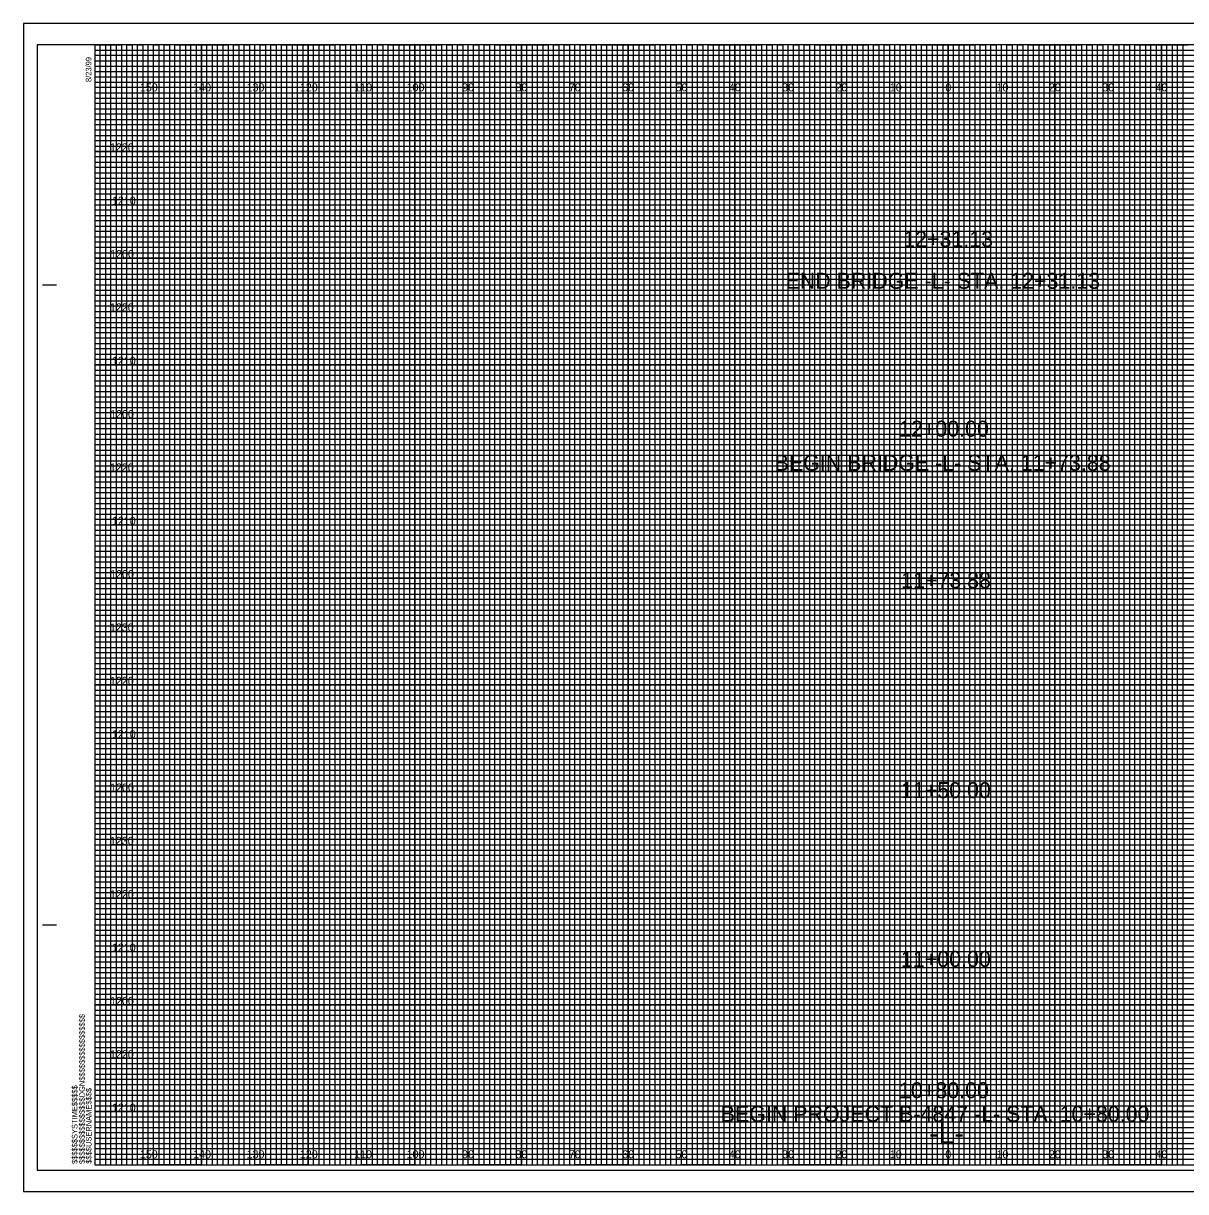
# Model space of a CAD drawing. Extents: x -13 to 375, y -5 to 214.
# Drawn here: x -13.4 to 204.5, y -5 to 214 of the extents above; entities that cross this region are included whole.
import ezdxf

# ---------------------------------------------------------------- set-up
doc = ezdxf.new("R2010")
doc.units = 0
for name, color, linetype in [('Default', 7, 'Continuous'), ('Prop XS Alignment Label', 7, 'Continuous'), ('Prop XS Elevation Labels', 7, 'Continuous'), ('Prop XS Offset Labels', 7, 'Continuous'), ('Prop XS Station Labels', 7, 'Continuous'), ('Sheet Cross Section CELL', 7, 'Continuous'), ('Sheet Cross Section Grid Major CELL', 7, 'Continuous'), ('Sheet Cross Section Grid Middle CELL', 7, 'Continuous'), ('Sheet Cross Section Grid Minor 1 CELL', 7, 'Continuous'), ('Sheet Cross Section Grid Minor 2 CELL', 7, 'Continuous'), ('Sheet Cutting Line CELL', 7, 'Continuous'), ('Sheet DOT Grid CELL', 7, 'Continuous'), ('Sheet Plot Border Inside CELL', 7, 'Continuous'), ('Sheet Plot Border Outside CELL', 7, 'Continuous')]:
    doc.layers.add(name, color=color, linetype=linetype)

msp = doc.modelspace()

# ---------------------------------------------------------------- linework, layer by layer
at = {"layer": 'Sheet Cross Section CELL'}
for p, q in [((-9.8, 165), (-7.3, 165)), ((-9.7, 165), (-7.2, 165)), ((-9.8, 45), (-7.3, 45)), ((-9.7, 45), (-7.2, 45)), ((0, 0), (0, 0)), ((0, 0), (0, 0)), ((0, 0), (0, 0)), ((0, 0), (0, 0)), ((0, 0), (0, 0)), ((0, 0), (0, 0)), ((0, 0), (0, 0))]:
    msp.add_line(p, q, dxfattribs=at)
msp.add_lwpolyline([(320, 210), (0, 210), (0, 0), (320, 0)], close=True, dxfattribs=at)
at = {"layer": 'Sheet Cross Section Grid Major CELL'}
for p, q in [((10, 210), (0, 210)), ((10, 0), (10, 210)), ((30, 210), (20, 210)), ((20, 210), (20, 0)), ((30, 0), (30, 210)), ((50, 210), (40, 210)), ((40, 210), (40, 0)), ((50, 0), (50, 210)), ((70, 210), (60, 210)), ((60, 210), (60, 0)), ((70, 0), (70, 210)), ((90, 210), (80, 210)), ((80, 210), (80, 0)), ((90, 0), (90, 210)), ((110, 210), (100, 210)), ((100, 210), (100, 0)), ((110, 0), (110, 210)), ((130, 210), (120, 210)), ((120, 210), (120, 0)), ((130, 0), (130, 210)), ((150, 210), (140, 210)), ((140, 210), (140, 0)), ((150, 0), (150, 210)), ((170, 210), (160, 210)), ((160, 210), (160, 0)), ((170, 0), (170, 210)), ((190, 210), (180, 210)), ((180, 210), (180, 0)), ((190, 0), (190, 210)), ((210, 210), (200, 210)), ((200, 210), (200, 0)), ((20, 0), (10, 0)), ((40, 0), (30, 0)), ((60, 0), (50, 0)), ((80, 0), (70, 0)), ((100, 0), (90, 0)), ((120, 0), (110, 0)), ((140, 0), (130, 0)), ((160, 0), (150, 0)), ((180, 0), (170, 0)), ((200, 0), (190, 0))]:
    msp.add_line(p, q, dxfattribs=at)
for points in [[(0, 200), (320, 200), (320, 190), (0, 190)], [(0, 180), (320, 180), (320, 170), (0, 170)], [(0, 160), (320, 160), (320, 150), (0, 150)], [(0, 140), (320, 140), (320, 130), (0, 130)], [(0, 120), (320, 120), (320, 110), (0, 110)], [(0, 100), (320, 100), (320, 90), (0, 90)], [(0, 80), (320, 80), (320, 70), (0, 70)], [(0, 60), (320, 60), (320, 50), (0, 50)], [(0, 40), (320, 40), (320, 30), (0, 30)], [(0, 20), (320, 20), (320, 10), (0, 10)]]:
    msp.add_lwpolyline(points, dxfattribs=at)
at = {"layer": 'Sheet Cross Section Grid Middle CELL'}
for points in [[(0, 210), (5, 210), (5, 0), (15, 0), (15, 210), (25, 210), (25, 0), (35, 0), (35, 210), (45, 210), (45, 0), (55, 0), (55, 210), (65, 210), (65, 0), (75, 0), (75, 210), (85, 210), (85, 0), (95, 0), (95, 210), (105, 210), (105, 0), (115, 0), (115, 210), (125, 210), (125, 0), (135, 0), (135, 210), (145, 210), (145, 0), (155, 0), (155, 210), (165, 210), (165, 0), (175, 0), (175, 210), (185, 210), (185, 0), (195, 0), (195, 210), (205, 210)], [(0, 205), (275, 205)], [(0, 185), (320, 185), (320, 195), (0, 195)], [(0, 165), (320, 165), (320, 175), (0, 175)], [(0, 145), (320, 145), (320, 155), (0, 155)], [(0, 125), (320, 125), (320, 135), (0, 135)], [(0, 105), (320, 105), (320, 115), (0, 115)], [(0, 85), (320, 85), (320, 95), (0, 95)], [(0, 65), (320, 65), (320, 75), (0, 75)], [(0, 45), (320, 45), (320, 55), (0, 55)], [(0, 25), (320, 25), (320, 35), (0, 35)], [(0, 5), (320, 5), (320, 15), (0, 15)]]:
    msp.add_lwpolyline(points, dxfattribs=at)
at = {"layer": 'Sheet Cross Section Grid Minor 1 CELL'}
for p, q in [((0, 209), (260, 209)), ((260, 207.98), (0, 207.98)), ((0, 207.98), (0, 207)), ((0, 207), (260, 207)), ((260, 205.89), (0, 205.89)), ((0, 205.89), (0, 204)), ((0, 204), (320, 204))]:
    msp.add_line(p, q, dxfattribs=at)
for points in [[(0, 203), (270, 203), (320, 203), (320, 202), (0, 202)], [(0, 201), (320, 201), (320, 199), (0, 199)], [(0, 198), (320, 198), (320, 197), (0, 196.98)], [(0, 196), (320, 196), (320, 194), (0, 194)], [(0, 193), (320, 193), (320, 192), (0, 192)], [(0, 191), (320, 191), (320, 189), (0, 189)], [(0, 188), (320, 188), (320, 187), (0, 187)], [(0, 186), (320, 186), (320, 184), (0, 184)], [(0, 183), (320, 183), (320, 182), (0, 182)], [(0, 181), (320, 181), (320, 179), (0, 179)], [(0, 178), (320, 178), (320, 177), (0, 177)], [(0, 176), (320, 176), (320, 173.95), (320, 173), (320, 172), (0, 172)], [(0, 174), (320, 174), (320, 173), (0, 173)], [(0, 171), (320, 171), (320, 169), (0, 169.03)], [(0, 169.03), (320, 169), (320, 168), (0, 168)], [(0, 167), (320, 167), (320, 166), (0, 166)], [(0, 164), (320, 164), (320, 163), (0, 163)], [(0, 162), (320, 162), (320, 161), (0, 161)], [(-0.07, 158.89), (320, 158.89), (320, 157.88), (-0.07, 157.88)], [(0, 157), (320, 157), (320, 156), (0, 156)], [(0, 154), (320, 154), (320, 153), (0, 153)], [(0, 152), (320, 152), (320, 151), (0, 151)], [(0, 149), (320, 149), (320, 148), (0, 148)], [(0, 147), (320, 147), (320, 146), (0, 146)], [(0, 144), (320, 144), (320, 143), (0, 143)], [(0, 142), (320, 142), (320, 141), (0, 141)], [(0, 139), (320, 139), (319.99, 137.98), (0, 138)], [(0, 137), (320, 137), (320, 136), (0, 136)], [(0, 134), (320, 134), (320, 133), (0, 133)], [(0, 132), (320, 132), (320, 131), (0, 131)], [(0, 129), (320, 129), (320, 128), (0, 128)], [(0, 127), (320, 127), (320, 126), (0, 126)], [(0, 124), (320, 124), (320, 123), (0, 123)], [(0, 122), (320, 122), (320, 121), (0, 121)], [(0, 119), (320, 119), (320, 118), (0, 118)], [(0, 116.99), (320.07, 116.91), (320, 116), (0, 116)], [(0, 114), (320, 114), (320, 113), (0, 113)], [(0, 112), (320, 112), (320, 111), (0, 111)], [(0, 109), (320, 109), (320, 108), (0, 108)], [(0, 107), (320, 107), (320, 106), (0, 106)], [(0, 104), (320, 104), (320, 103), (0, 103)], [(0, 102), (320, 102), (320, 101), (0, 101)], [(0, 99), (320, 99), (320, 98), (0, 98)], [(0, 97), (320, 97), (320, 96), (0, 96)], [(0, 94), (320, 94), (320, 93), (0, 93)], [(0, 92), (320, 92), (320, 91), (0, 91)], [(0, 89), (320, 89), (320, 88), (0, 88)], [(0, 87), (320, 87), (320, 86), (0, 86)], [(0, 84), (320, 84), (320, 83), (0, 83)], [(0, 82), (320, 82), (320, 81), (0, 81)], [(0, 79), (320, 79), (319.99, 77.98), (0, 78)], [(0, 77), (320, 77), (320, 76), (0, 76)], [(0, 74), (320, 74), (320, 73), (0, 73)], [(0, 72), (320, 72), (320, 71), (0, 71)], [(0, 69), (320, 69), (320, 68), (0, 68)], [(0, 67), (320, 67), (320, 66), (0, 66)], [(0, 64), (320, 64), (320, 63), (0, 63)], [(0, 62), (320, 62), (320, 61), (0, 61)], [(0, 59), (320, 59), (320, 58), (0, 58)], [(0, 56.99), (320.07, 56.91), (320, 56), (0, 56)], [(0, 54), (320, 54), (320, 53), (0, 53)], [(0, 52), (320, 52), (320, 51), (0, 51)], [(0, 49), (320, 49), (320, 48), (0, 48)], [(0, 47), (320, 47), (320, 46), (0, 46)], [(0, 44), (320, 44), (320, 43), (0, 43)], [(0, 42), (320, 42), (320, 41), (0, 41)], [(0, 39), (320, 39), (320, 38), (0, 38)], [(0, 37), (320, 37), (320, 36), (0, 36)], [(0, 34), (320, 34), (320, 33), (0, 33)], [(0, 32), (320, 32), (320, 31), (0, 31)], [(0, 29), (320, 29), (320, 28), (0, 28)], [(0, 27), (320, 27), (320, 26), (0, 26)], [(0, 24), (320, 24), (320, 23), (0, 23)], [(0, 22), (320, 22), (320, 21), (0, 21)], [(0, 19), (320, 19), (320, 18), (0, 18)], [(0, 17), (320, 17), (320, 16), (0, 16)], [(0, 14), (320, 14), (320, 13), (0, 13)], [(0, 12), (320, 12), (320, 11), (0, 11)], [(0, 9), (320, 9), (320, 8), (0, 8)], [(0, 7), (320, 7), (320, 6), (0, 6)], [(0, 4), (320, 4), (320, 3), (0, 3)], [(0, 2), (320, 2), (320, 1), (0, 1)]]:
    msp.add_lwpolyline(points, dxfattribs=at)
at = {"layer": 'Sheet Cross Section Grid Minor 2 CELL'}
for points in [[(0, 0), (1, 0), (1, 210), (2, 210), (2, 0)], [(2, 0), (3, 0), (3, 210), (4, 210), (4, 0)], [(5, 0), (6, 0), (6, 210), (7, 210), (7, 0)], [(7, 0), (8, 0), (8, 210), (9, 210), (9, 0)], [(10, 0), (11, 0), (11, 210), (12, 210), (12, 0)], [(12, 0), (13, 0), (13, 210), (14, 210), (14, 0)], [(15, 0), (16, 0), (16, 210), (17, 210), (17, 0)], [(17, 0), (18, 0), (18, 210), (19, 210), (19, 0)], [(20, 0), (21, 0), (21, 210), (22, 210), (22, 0)], [(22, 0), (23, 0), (23, 210), (24, 210), (24, 0)], [(25, 0), (26, 0), (26, 210), (27, 210), (27, 0)], [(27, 0), (28, 0), (28, 210), (29, 210), (29, 0)], [(30, 0), (31, 0), (31, 210), (32, 210), (32, 0)], [(32, 0), (33, 0), (33, 210), (34, 210), (34, 0)], [(35, 0), (36, 0), (36, 210), (37, 210), (37, 0)], [(37, 0), (38, 0), (38, 210), (39, 210), (39, 0)], [(40, 0), (41, 0), (41, 210), (42, 210), (42, 0)], [(42, 0), (43, 0), (43, 210), (44, 210), (44, 0)], [(45, 0), (46, 0), (46, 210), (47, 210), (47, 0)], [(47, 0), (48, 0), (48, 210), (49, 210), (49, 0)], [(50, 0), (51, 0), (51, 210), (52, 210), (52, 0)], [(52, 0), (53, 0), (53, 210), (54, 210), (54, 0)], [(55, 0), (56, 0), (56, 210), (57, 210), (57, 0)], [(57, 0), (58, 0), (58, 210), (59, 210), (59, 0)], [(60, 0), (61, 0), (61, 210), (62, 210), (62, 0)], [(62, 0), (63, 0), (63, 210), (64, 210), (64, 0)], [(65, 0), (66, 0), (66, 210), (67, 210), (67, 0)], [(67, 0), (68, 0), (68, 210), (69, 210), (69, 0)], [(70, 0), (71, 0), (71, 210), (72, 210), (72, 0)], [(72, 0), (73, 0), (73, 210), (74, 210), (74, 0)], [(75, 0), (76, 0), (76, 210), (77, 210), (77, 0)], [(77, 0), (78, 0), (78, 210), (79, 210), (79, 0)], [(80, 0), (81, 0), (81, 210), (82, 210), (82, 0)], [(82, 0), (83, 0), (83, 210), (84, 210), (84, 0)], [(85, 0), (86, 0), (86, 210), (87, 210), (87, 0)], [(87, 0), (88, 0), (88, 210), (89, 210), (89, 0)], [(90, 0), (91, 0), (91, 210), (92, 210), (92, 0)], [(92, 0), (93, 0), (93, 210), (94, 210), (94, 0)], [(95, 0), (96, 0), (96, 210), (97, 210), (97, 0)], [(97, 0), (98, 0), (98, 210), (99, 210), (99, 0)], [(100, 0), (101, 0), (101, 210), (102, 210), (102, 0)], [(102, 0), (103, 0), (103, 210), (104, 210), (104, 0)], [(105, 0), (106, 0), (106, 210), (107, 210), (107, 0)], [(107, 0), (108, 0), (108, 210), (109, 210), (109, 0)], [(110, 0), (111, 0), (111, 210), (112, 210), (112, 0)], [(112, 0), (113, 0), (113, 210), (114, 210), (114, 0)], [(115, 0), (116, 0), (116, 210), (117, 210), (117, 0)], [(117, 0), (118, 0), (118, 210), (119, 210), (119, 0)], [(120, 0), (121, 0), (121, 210), (122, 210), (122, 0)], [(122, 0), (123, 0), (123, 210), (124, 210), (124, 0)], [(125, 0), (126, 0), (126, 210), (127, 210), (127, 0)], [(127, 0), (128, 0), (128, 210), (129, 210), (129, 0)], [(130, 0), (131, 0), (131, 210), (132, 210), (132, 0)], [(132, 0), (133, 0), (133, 210), (134, 210), (134, 0)], [(135, 0), (136, 0), (136, 210), (137, 210), (137, 0)], [(137, 0), (138, 0), (138, 210), (139, 210), (139, 0)], [(140, 0), (141, 0), (141, 210), (142, 210), (142, 0)], [(142, 0), (143, 0), (143, 210), (144, 210), (144, 0)], [(145, 0), (146, 0), (146, 210), (147, 210), (147, 0)], [(147, 0), (148, 0), (148, 210), (149, 210), (149, 0)], [(150, 0), (151, 0), (151, 210), (152, 210), (152, 0)], [(152, 0), (153, 0), (153, 210), (154, 210), (154, 0)], [(155, 0), (156, 0), (156, 210), (157, 210), (157, 0)], [(157, 0), (158, 0), (158, 210), (159, 210), (159, 0)], [(160, 0), (161, 0), (161, 210), (162, 210), (162, 0)], [(162, 0), (163, 0), (163, 210), (164, 210), (164, 0)], [(165, 0), (166, 0), (166, 210), (167, 210), (167, 0)], [(167, 0), (168, 0), (168, 210), (169, 210), (169, 0)], [(170, 0), (171, 0), (171, 210), (172, 210), (172, 0)], [(172, 0), (173, 0), (173, 210), (174, 210), (174, 0)], [(175, 0), (176, 0), (176, 210), (177, 210), (177, 0)], [(177, 0), (178, 0), (178, 210), (179, 210), (179, 0)], [(180, 0), (181, 0), (181, 210), (182, 210), (182, 0)], [(182, 0), (183, 0), (183, 210), (184, 210), (184, 0)], [(185, 0), (186, 0), (186, 210), (187, 210), (187, 0)], [(187, 0), (188, 0), (188, 210), (189, 210), (189, 0)], [(190, 0), (191, 0), (191, 210), (192, 210), (192, 0)], [(192, 0), (193, 0), (193, 210), (194, 210), (194, 0)], [(195, 0), (196, 0), (196, 210), (197, 210), (197, 0)], [(197, 0), (198, 0), (198, 210), (199, 210), (199, 0)], [(200, 0), (201, 0), (201, 210), (202, 210), (202, 0)], [(202, 0), (203, 0), (203, 210), (204, 210), (204, 0)]]:
    msp.add_lwpolyline(points, dxfattribs=at)
at = {"layer": 'Sheet Cutting Line CELL'}
for p, q in [((323.3, 214), (-13.4, 214)), ((-13.4, 214), (-13.4, -5)), ((-13.4, -5), (323.3, -5))]:
    msp.add_line(p, q, dxfattribs=at)
at = {"layer": 'Sheet DOT Grid CELL'}
for p, q in [((10, 0), (10, 210)), ((20, 0), (20, 210)), ((30, 0), (30, 210)), ((40, 0), (40, 210)), ((50, 0), (50, 210)), ((60, 0), (60, 210)), ((70, 0), (70, 210)), ((80, 0), (80, 210)), ((90, 0), (90, 210)), ((100, 0), (100, 210)), ((110, 0), (110, 210)), ((120, 0), (120, 210)), ((130, 0), (130, 210)), ((140, 0), (140, 210)), ((150, 0), (150, 210)), ((160, 0), (160, 210)), ((170, 0), (170, 210)), ((180, 0), (180, 210)), ((190, 0), (190, 210)), ((200, 0), (200, 210)), ((0, 200), (320, 200)), ((0, 190), (320, 190)), ((0, 180), (320, 180)), ((0, 170), (320, 170)), ((0, 160), (320, 160)), ((0, 150), (320, 150)), ((0, 140), (320, 140)), ((0, 130), (320, 130)), ((0, 120), (320, 120)), ((0, 110), (320, 110)), ((0, 100), (320, 100)), ((0, 90), (320, 90)), ((0, 80), (320, 80)), ((0, 70), (320, 70)), ((0, 60), (320, 60)), ((0, 50), (320, 50)), ((0, 40), (320, 40)), ((0, 30), (320, 30)), ((0, 20), (320, 20)), ((0, 10), (320, 10))]:
    msp.add_line(p, q, dxfattribs=at)
at = {"layer": 'Sheet Plot Border Inside CELL'}
msp.add_lwpolyline([(-10.8, -1), (322.4, -1), (322.4, 210), (-10.8, 210)], close=True, dxfattribs=at)
at = {"layer": 'Sheet Plot Border Outside CELL'}
msp.add_lwpolyline([(-13.4, -5), (323.3, -5), (323.3, 214), (-13.4, 214)], close=True, dxfattribs=at)

# ---------------------------------------------------------------- texts
at = {"layer": 'Default'}
for s, p in [('END BRIDGE -L- STA. 12+31.13', (129.48, 164.25)), ('BEGIN BRIDGE -L- STA. 11+73.88', (127.45, 130.14)), ('BEGIN PROJECT B-4847 -L- STA. 10+80.00', (117.34, 8.08))]:
    msp.add_text(s, height=3, dxfattribs=at).set_placement(p)
at = {"layer": 'Prop XS Alignment Label'}
msp.add_text('-L-', height=4, dxfattribs=at).set_placement((156.42, 4))
at = {"layer": 'Prop XS Elevation Labels'}
for s, p in [('1220', (2.83, 190)), ('1210', (3.2, 180)), ('1200', (2.87, 170)), ('1220', (2.83, 160)), ('1210', (3.2, 150)), ('1200', (2.87, 140)), ('1220', (2.83, 130)), ('1210', (3.2, 120)), ('1200', (2.87, 110)), ('1230', (2.82, 100)), ('1220', (2.83, 90)), ('1210', (3.2, 80)), ('1200', (2.87, 70)), ('1230', (2.82, 60)), ('1220', (2.83, 50)), ('1210', (3.2, 40)), ('1200', (2.87, 30)), ('1220', (2.83, 20)), ('1210', (3.2, 10))]:
    msp.add_text(s, height=1.5, dxfattribs=at).set_placement(p)
at = {"layer": 'Prop XS Offset Labels'}
for s, p in [('150', (8.44, 201.25)), ('140', (18.44, 201.25)), ('130', (28.44, 201.25)), ('120', (38.44, 201.25)), ('110', (48.62, 201.25)), ('100', (58.44, 201.25)), ('90', (68.86, 201.25)), ('80', (78.86, 201.25)), ('70', (88.86, 201.25)), ('60', (98.86, 201.25)), ('50', (108.86, 201.25)), ('40', (118.86, 201.25)), ('30', (128.86, 201.25)), ('20', (138.86, 201.25)), ('10', (149.04, 201.25)), ('0', (159.45, 201.25)), ('0', (159.45, 201.25)), ('10', (169.04, 201.25)), ('20', (178.86, 201.25)), ('30', (188.86, 201.25)), ('40', (198.86, 201.25)), ('150', (8.44, 1.25)), ('140', (18.44, 1.25)), ('130', (28.44, 1.25)), ('120', (38.44, 1.25)), ('110', (48.62, 1.25)), ('100', (58.44, 1.25)), ('90', (68.86, 1.25)), ('80', (78.86, 1.25)), ('70', (88.86, 1.25)), ('60', (98.86, 1.25)), ('50', (108.86, 1.25)), ('40', (118.86, 1.25)), ('30', (128.86, 1.25)), ('20', (138.86, 1.25)), ('10', (149.04, 1.25)), ('0', (159.45, 1.25)), ('0', (159.45, 1.25)), ('10', (169.04, 1.25)), ('20', (178.86, 1.25)), ('30', (188.86, 1.25)), ('40', (198.86, 1.25))]:
    msp.add_text(s, height=1.5, dxfattribs=at).set_placement(p)
at = {"layer": 'Prop XS Station Labels'}
for s, p in [('12+31.13', (151.56, 172.07)), ('12+00.00', (150.77, 136.52)), ('11+73.88', (151.16, 108.12)), ('11+50.00', (151.13, 68.76)), ('11+00.00', (151.13, 37.12)), ('10+80.00', (150.77, 12.51))]:
    msp.add_text(s, height=3, dxfattribs=at).set_placement(p)
at = {"layer": 'Sheet Cross Section CELL'}
for s, p in [('8/23/99', (-0.65, 203)), ('$$$$$$$$$$$$$$$$DGN$$$$$$$$$$$$$$$$', (-1.88, 0.18)), ('$$$$$$SYSTIME$$$$$', (-3.26, 0.18)), ('$$$$USERNAME$$$$', (-0.62, 0.23))]:
    msp.add_text(s, height=1.05, rotation=90, dxfattribs=at).set_placement(p)

doc.saveas('drawing.dxf')
